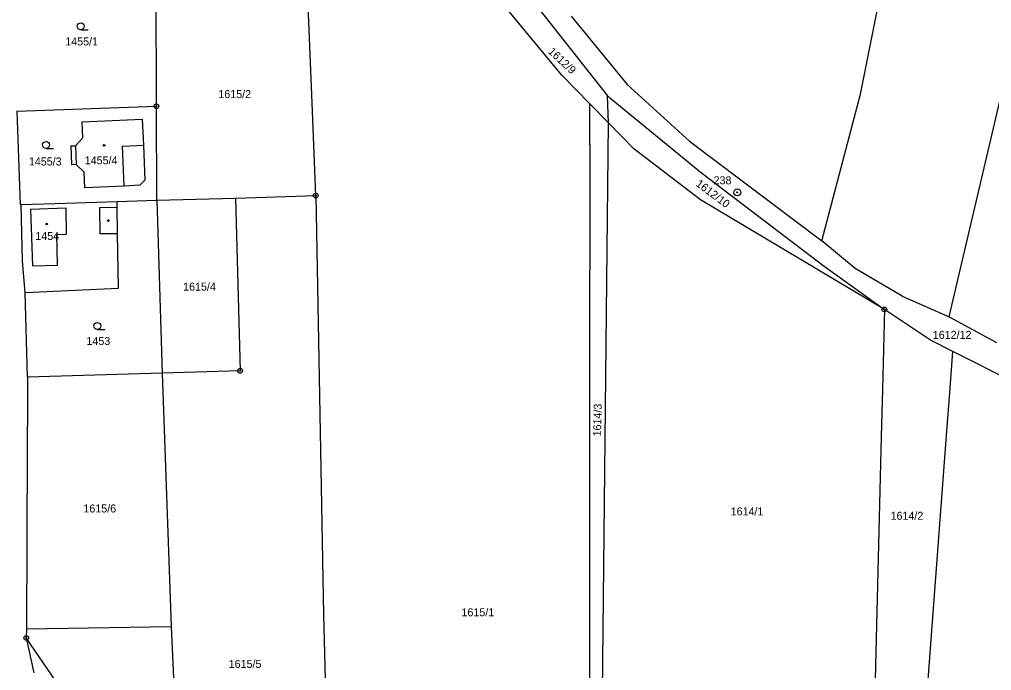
# Model space of a CAD drawing. Extents: x -763296 to -761805, y -1153670 to -1152034.
# Drawn here: x -762755.5 to -762549.1, y -1152539 to -1152400.8 of the extents above; entities that cross this region are included whole.
import ezdxf

# ---------------------------------------------------------------- set-up
doc = ezdxf.new("R2010")
doc.units = 0
for name, color, linetype in [('Vrstva 1', 7, 'Continuous'), ('Vrstva 17', 7, 'Continuous'), ('Vrstva 18', 7, 'Continuous'), ('Vrstva 19', 7, 'Continuous'), ('Vrstva 24', 7, 'Continuous'), ('Vrstva 25', 7, 'Continuous'), ('Vrstva 4', 7, 'Continuous'), ('Vrstva 6', 7, 'Continuous')]:
    doc.layers.add(name, color=color, linetype=linetype)

msp = doc.modelspace()

# ---------------------------------------------------------------- linework, layer by layer
at = {"layer": 'Vrstva 1'}
for p, q in [((-762726.42, -1152417.35), (-762726.49, -1152394.53)), ((-762693.4, -1152416.82), (-762694.27, -1152395.38)), ((-762640.33, -1152412.61), (-762652.6, -1152397.81)), ((-762634.38, -1152418.72), (-762640.33, -1152412.61)), ((-762726.41, -1152419.22), (-762726.42, -1152417.35)), ((-762692.58, -1152438.2), (-762693.4, -1152416.82)), ((-762756.02, -1152420.25), (-762726.41, -1152419.22)), ((-762726.34, -1152439.2), (-762726.41, -1152419.22)), ((-762634.39, -1152427.39), (-762634.38, -1152418.72)), ((-762630.45, -1152422.76), (-762634.38, -1152418.72)), ((-762756.02, -1152420.25), (-762755.36, -1152440.1)), ((-762742.19, -1152422.52), (-762729.42, -1152421.96)), ((-762729.42, -1152421.96), (-762729.16, -1152427.48)), ((-762742.06, -1152425.95), (-762742.19, -1152422.52)), ((-762625.06, -1152428.3), (-762630.45, -1152422.76)), ((-762743.56, -1152427.61), (-762742.06, -1152425.95)), ((-762744.53, -1152427.64), (-762743.56, -1152427.61)), ((-762744.35, -1152431.66), (-762744.53, -1152427.64)), ((-762729.16, -1152427.48), (-762728.86, -1152434.89)), ((-762634.39, -1152427.39), (-762634.43, -1152480.71)), ((-762610.86, -1152439.09), (-762625.06, -1152428.3)), ((-762743.42, -1152431.6), (-762744.35, -1152431.66)), ((-762741.73, -1152433.21), (-762743.42, -1152431.6)), ((-762741.58, -1152436.57), (-762741.73, -1152433.21)), ((-762733.29, -1152436.18), (-762741.58, -1152436.57)), ((-762729.9, -1152435.97), (-762733.29, -1152436.18)), ((-762728.86, -1152434.89), (-762729.9, -1152435.97)), ((-762726.34, -1152439.2), (-762709.6, -1152438.71)), ((-762709.6, -1152438.71), (-762692.58, -1152438.2)), ((-762709.6, -1152438.71), (-762708.64, -1152475.4)), ((-762755.36, -1152440.1), (-762755.16, -1152440.07)), ((-762755.16, -1152440.07), (-762745.59, -1152439.78)), ((-762754.88, -1152452.13), (-762755.16, -1152440.07)), ((-762745.59, -1152439.78), (-762734.75, -1152439.45)), ((-762734.75, -1152439.45), (-762726.34, -1152439.2)), ((-762734.73, -1152440.64), (-762734.75, -1152439.45)), ((-762734.65, -1152446.28), (-762734.73, -1152440.64)), ((-762726.34, -1152439.2), (-762725.21, -1152475.88)), ((-762571.86, -1152462.37), (-762610.86, -1152439.09)), ((-762734.48, -1152457.82), (-762734.65, -1152446.28)), ((-762754.28, -1152458.75), (-762754.88, -1152452.13)), ((-762754.28, -1152458.75), (-762734.48, -1152457.82)), ((-762753.79, -1152476.76), (-762754.28, -1152458.75)), ((-762571.86, -1152462.37), (-762572.28, -1152479.33)), ((-762562.04, -1152468.88), (-762571.86, -1152462.37)), ((-762557.33, -1152471.3), (-762562.04, -1152468.88)), ((-762557.91, -1152479.08), (-762557.33, -1152471.3)), ((-762542.4, -1152478.84), (-762557.33, -1152471.3)), ((-762725.21, -1152475.88), (-762753.79, -1152476.76)), ((-762708.64, -1152475.4), (-762725.21, -1152475.88)), ((-762753.79, -1152476.76), (-762753.81, -1152482.05)), ((-762572.28, -1152479.33), (-762572.52, -1152489.33)), ((-762558.66, -1152489.1), (-762557.91, -1152479.08)), ((-762753.81, -1152482.05), (-762753.86, -1152492.05)), ((-762634.43, -1152480.71), (-762634.44, -1152490.71)), ((-762572.52, -1152489.33), (-762574.04, -1152550.81)), ((-762563.28, -1152550.87), (-762558.66, -1152489.1)), ((-762753.86, -1152492.05), (-762754.03, -1152530.18)), ((-762634.44, -1152490.71), (-762634.54, -1152614.04)), ((-762754.03, -1152530.18), (-762754.04, -1152532.11)), ((-762754.04, -1152532.11), (-762752.45, -1152539.49)), ((-762721.02, -1152580.29), (-762754.04, -1152532.11))]:
    msp.add_line(p, q, dxfattribs=at)
at = {"layer": 'Vrstva 24'}
for centre, radius in [((-762726.41, -1152419.22), 0.5), ((-762726.41, -1152419.22), 0.1), ((-762692.58, -1152438.2), 0.5), ((-762692.58, -1152438.2), 0.1), ((-762603.08, -1152437.52), 0.75), ((-762603.08, -1152437.52), 0.1), ((-762571.86, -1152462.37), 0.5), ((-762571.86, -1152462.37), 0.1), ((-762708.64, -1152475.4), 0.5), ((-762708.64, -1152475.4), 0.1), ((-762754.04, -1152532.11), 0.5), ((-762754.04, -1152532.11), 0.1)]:
    msp.add_circle(centre, radius, dxfattribs=at)
at = {"layer": 'Vrstva 25'}
for p, q in [((-762742.48, -1152403), (-762740.88, -1152403)), ((-762749.84, -1152428.19), (-762748.24, -1152428.19)), ((-762738.97, -1152466.62), (-762737.37, -1152466.62))]:
    msp.add_line(p, q, dxfattribs=at)
for centre, radius in [((-762742.48, -1152402.25), 0.75), ((-762749.84, -1152427.44), 0.75), ((-762737.52, -1152427.54), 0.175), ((-762749.72, -1152444.24), 0.175), ((-762736.62, -1152443.49), 0.175), ((-762738.97, -1152465.87), 0.75)]:
    msp.add_circle(centre, radius, dxfattribs=at)
at = {"layer": 'Vrstva 4'}
for p, q in [((-762743.56, -1152427.61), (-762743.42, -1152431.6)), ((-762733.62, -1152427.69), (-762729.16, -1152427.48)), ((-762733.29, -1152436.18), (-762733.62, -1152427.69)), ((-762753.15, -1152441.08), (-762745.58, -1152440.82)), ((-762745.51, -1152446.41), (-762745.58, -1152440.82)), ((-762738.45, -1152440.69), (-762734.73, -1152440.64)), ((-762738.39, -1152446.33), (-762738.45, -1152440.69)), ((-762753.15, -1152441.08), (-762752.74, -1152453.13)), ((-762747.57, -1152446.46), (-762745.51, -1152446.41)), ((-762747.41, -1152453), (-762747.57, -1152446.46)), ((-762734.65, -1152446.28), (-762738.39, -1152446.33)), ((-762752.74, -1152453.13), (-762747.41, -1152453))]:
    msp.add_line(p, q, dxfattribs=at)
at = {"layer": 'Vrstva 6'}
for p, q in [((-762576.94, -1152416.63), (-762561.68, -1152340.97)), ((-762645.21, -1152398.54), (-762630.65, -1152416.99)), ((-762638.33, -1152400.1), (-762626.43, -1152414.62)), ((-762626.43, -1152414.62), (-762613.21, -1152426.65)), ((-762558.07, -1152463.9), (-762546.74, -1152415.72)), ((-762630.45, -1152422.76), (-762630.65, -1152416.99)), ((-762630.65, -1152416.99), (-762610.68, -1152433.38)), ((-762585.16, -1152447.77), (-762576.94, -1152416.63)), ((-762632.44, -1152612.71), (-762630.45, -1152422.76)), ((-762613.21, -1152426.65), (-762585.16, -1152447.77)), ((-762610.68, -1152433.38), (-762584.63, -1152453.2)), ((-762692.58, -1152438.2), (-762690.96, -1152527.16)), ((-762578.04, -1152453.68), (-762585.16, -1152447.77)), ((-762584.63, -1152453.2), (-762571.86, -1152462.37)), ((-762568.05, -1152459.54), (-762578.04, -1152453.68)), ((-762568.05, -1152459.54), (-762558.07, -1152463.9)), ((-762558.07, -1152463.9), (-762548.03, -1152469.36)), ((-762725.21, -1152475.88), (-762723.25, -1152529.67)), ((-762690.96, -1152527.16), (-762688.39, -1152627.94)), ((-762754.03, -1152530.18), (-762723.25, -1152529.67)), ((-762723.25, -1152529.67), (-762721.02, -1152580.29))]:
    msp.add_line(p, q, dxfattribs=at)

# ---------------------------------------------------------------- texts
at = {"layer": 'Vrstva 17'}
msp.add_text('238', height=1.7, dxfattribs=at).set_placement((-762608.114, -1152435.8))
at = {"layer": 'Vrstva 18'}
for s, p in [('1455/1', (-762745.77, -1152406.32)), ('1615/2', (-762713.267, -1152417.5)), ('1455/3', (-762753.495, -1152431.8)), ('1615/4', (-762720.743, -1152458.37)), ('1612/12', (-762561.575, -1152468.61)), ('1453', (-762741.269, -1152469.92)), ('1615/6', (-762741.923, -1152505.47)), ('1614/1', (-762604.488, -1152506.09)), ('1614/2', (-762570.54, -1152507.02)), ('1615/1', (-762661.645, -1152527.51)), ('1615/5', (-762711.07, -1152538.47))]:
    msp.add_text(s, height=1.7, dxfattribs=at).set_placement(p)
for s, rotation, p in [('1612/9', 316.84566, (-762643.373, -1152407.786)), ('1612/10', 323.0909, (-762612.033, -1152435.997)), ('1614/3', 88.75116, (-762632.007, -1152489.343))]:
    msp.add_text(s, height=1.7, rotation=rotation, dxfattribs=at).set_placement(p)
at = {"layer": 'Vrstva 19'}
for s, p in [('1455/4', (-762741.628, -1152431.56)), ('1454', (-762752.122, -1152447.62))]:
    msp.add_text(s, height=1.7, dxfattribs=at).set_placement(p)

doc.saveas('drawing.dxf')
